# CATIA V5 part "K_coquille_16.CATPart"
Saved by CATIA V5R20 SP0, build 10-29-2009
Part number: coquille 16
Bounding box of the stored display mesh (mm): x -239.853 to 239.853, y -450 to -358, z -239.86 to 239.86
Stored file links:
  G:\Khaled_CFAO_2011\ST2M\ST2M_GR1\mponsin\Khaled\CAD_ThinkMOTION\K_coquille_16.CATPart
  C:\Users\Socar\Documents\thinkmotion\Final\Diff2.CATProduct
  G:\Khaled_CFAO_2011\ST2M\ST2M_GR1\mponsin\Khaled\CAD_ThinkMOTION\K_mponsin.CATProduct
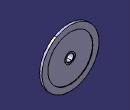
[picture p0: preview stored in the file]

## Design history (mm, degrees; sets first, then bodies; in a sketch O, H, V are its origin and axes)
External parameters (linked from other documents)
  `External.R cardan` = 30 mm
  `External.R palier` = 70 mm
Set1
  DatumPoint1 to DatumPoint6: linked copy from another document
  Plane1 "debut 16": linked copy from another document
  Line1 "axe general": linked copy from another document
Body1 (main body)
  Sketch1 on yz-plane, origin (0, 0, 0), H (0, 1, 0), V (0, 0, 1)
    line L1 (-378, 239.8651) -> (-358, 239.8651)
    point P2 (-358, 239.8651)
    line L2 (-358, 239.8651) -> (-358, 189.8651)
    point P3 (-358, 189.8651)
    line L3 (-358, 189.8651) -> (-363, 189.8651)
    point P4 (-363, 189.8651)
    line L4 (-363, 189.8651) -> (-363, 43)
    line L5 (-363, 43) -> (-360, 43)
    point P6 (-360, 43)
    line L6 (-360, 43) -> (-360, 33)
    point P7 (-360, 33)
    line L7 (-360, 33) -> (-364, 33)
    point P8 (-364, 33)
    line L8 (-364, 33) -> (-364, 30)
    line L9 (-364, 30) -> (-450, 30)
    line L10 (-450, 30) -> (-450, 70)
    line L11 (-450, 70) -> (-378, 70)
    line L12 (-378, 70) -> (-378, 239.8651)
    reference projected point E1 (-358, 189.8651) from vertex of DatumPoint1
    reference projected point E2 (-358, 239.8651) from vertex of DatumPoint2
    reference projected point E3 (-363, 189.8651) from vertex of DatumPoint3
    reference projected point E4 (-360, 33) from vertex of DatumPoint4
    reference projected point E5 (-360, 43) from vertex of DatumPoint5
    reference projected point E6 (-364, 33) from vertex of DatumPoint6
    reference intersected line E7 through (-450, 0) direction (0, 1) from Plane1
    reference projected line E8 through (0, 0) direction (1, 0) from Line1
    reference projected line E9 through (0, 0) direction (1, 0) from Line1
    reference projected line E10 through (0, 0) direction (1, 0) from Line1
    reference projected line E11 through (0, 0) direction (1, 0) from Line1
    distance L4 L12 = 15
    distance E8 L9 = 30 {= `External.R cardan`}
    distance E9 E10 = 0 (reference)
    distance E11 L11 = 70 {= `External.R palier`}
    horizontal: L1 H, L3 H, L5 H, L7 H, L9 H, L11 H
    vertical: L2 V, L4 V, L6 V, L8 V, L10 V, L12 V
    coincidence: E1 P3, P2 E2, E3 P4, E4 P7, E5 P6, E6 P8, E7 L10
  Shaft1: profile Sketch1, axis Line1, angle 360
